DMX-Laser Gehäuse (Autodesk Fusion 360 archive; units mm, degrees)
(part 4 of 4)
pcbextrude "Leiterplatte extrudieren1" HoleDepth 1.606 HoleDiameter 2.3 TipAngle 10313.2 HoleDepth 1.606 HoleDiameter 2.3 TipAngle 10313.2
pcbextrude "Leiterplatte extrudieren1" HoleDepth 1.606 HoleDiameter 2.3 TipAngle 10313.2 HoleDepth 1.606 HoleDiameter 2.3 TipAngle 10313.2 HoleDepth 1.606 HoleDiameter 2.3 TipAngle 10313.2
extrude "Extrusion" sketch "Skizze" blind 1.5 HoleDepth 1.606 HoleDiameter 2.3 TipAngle 10313.2 bodies "Leiterplatte"
pcbextrude "Leiterplatte extrudieren1"
pcbextrude "Leiterplatte extrudieren2"
create_component "Komponente erstellen1"
create_component "Komponente erstellen2"
create_component "Komponente erstellen3"
create_component "Komponente erstellen4"
create_component "Komponente erstellen5"
create_component "Komponente erstellen6"
create_component "Komponente erstellen1"
create_component "Komponente erstellen2"
create_component "Komponente erstellen3"
create_component "Komponente erstellen1"
create_component "Komponente erstellen4"
create_component "Komponente erstellen1"
create_component "Komponente erstellen5"
create_component "Komponente erstellen1"
create_component "Komponente erstellen6"
create_component "Komponente erstellen7"
create_component "Komponente erstellen8"
create_component "Komponente erstellen9"
create_component "Komponente erstellen10"
create_component "Komponente erstellen1"
create_component "Komponente erstellen11"
create_component "Komponente erstellen1"
create_component "Komponente erstellen12"
create_component "Komponente erstellen13"
create_component "Komponente erstellen14"
as_built_joint "Bestand"
create_component "Komponente erstellen17"
create_component "Komponente erstellen1"
named bodies: "Leiterplatte"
